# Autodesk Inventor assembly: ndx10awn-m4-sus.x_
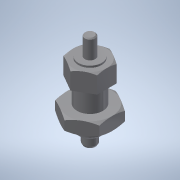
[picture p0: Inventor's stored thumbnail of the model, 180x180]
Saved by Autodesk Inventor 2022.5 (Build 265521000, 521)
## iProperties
Part Number: ndx10awn-m4-sus.x_
Material: 一般
Document SubType Name: Assembly
Designer: ImaoCorp
Sending System: SOLIDWORKS 2017-2017317
MC: AMD64
MC_MODEL: Intel64 Family 6 Model 60 Stepping 3, GenuineIntel
OS: Windows_NT
FRU: Parasolid Version 29.0, build 201,  4-17-2017
FORMAT: text
GUISE: transmit
KEY: ndx10awn-m4-sus
FILE: ndx10awn-m4-sus.x_t
DATE: Wed Sep 04 15:31:33 2019
Author: ImaoCorp
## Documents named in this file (3)
- X:\14_SW2022-Inv2022\00_全2023-1023新製品(TCC)まで\n\ndx10awn-m4-sus\NDX10AWN-M4-SUS.iam
- X:\14_SW2022-Inv2022\00_全2023-1023新製品(TCC)まで\n\ndx10awn-m4-sus\ndx10awn-m4-sus_01.ipt
- X:\14_SW2022-Inv2022\00_全2023-1023新製品(TCC)まで\n\ndx10awn-m4-sus\ndx10awn-m4-sus_02.ipt
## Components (2 placed, 2 different names)
1. ndx10awn-m4-sus_01
2. ndx10awn-m4-sus_02
